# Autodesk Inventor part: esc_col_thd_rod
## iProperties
Shininess: 64.0
Length Units: 11269
Angle Units: 11279
Time Units: 11290
Mass Units: 11283
Length Display Precision: 3
Angle Display Precision: 2
Compacted: True
Part Number: esc_col_thd_rod
Document SubType Name: Modeling
Created: 2004-08
Material: Stainless Steel, Austenitic
Designer: John Blackburn
Manufacturer: Standard
Standards Organization: Custom
Density: 0.0
Volumn: 0.0
Area: 0.0
PropertySet Name: Model Information
Control State: 0
Master: False
Checked Out: False
Author: John Blackburn
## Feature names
1. Extrusion1
2. Chamfer1
